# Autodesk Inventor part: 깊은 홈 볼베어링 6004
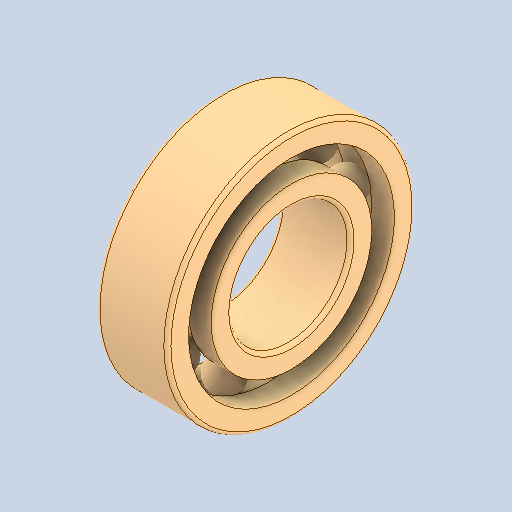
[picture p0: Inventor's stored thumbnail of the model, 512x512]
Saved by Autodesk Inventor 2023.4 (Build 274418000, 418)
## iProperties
Created: 2024-09
Part Number: 깊은 홈 볼베어링 6004
Material: 강철, 연강
Description: 깊은 그루브 볼 베어링
Document SubType Name: Modeling
Designer: 11
Density: 7.85 g/cm^3
Appearance: 기본값
Author: jhkim
Sending System: Autodesk Inventor 2025
Preprocessor: ST-DEVELOPER v20
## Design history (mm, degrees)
node "깊은 홈 볼베어링 60041"
node "솔리드1"
node "솔리드2"
node "솔리드3"
node "솔리드4"
node "솔리드5"
node "솔리드6"
node "솔리드7"
node "솔리드8"
node "솔리드9"
node "솔리드10"
node "솔리드11"
body "Solid1"
node "Solid1:1"
node "Solid1:2"
node "Solid1:3"
node "Solid1:4"
node "Solid1:5"
node "Solid1:6"
node "Solid1:7"
node "Solid1:8"
node "Solid1:9"
node "Solid1:10"
